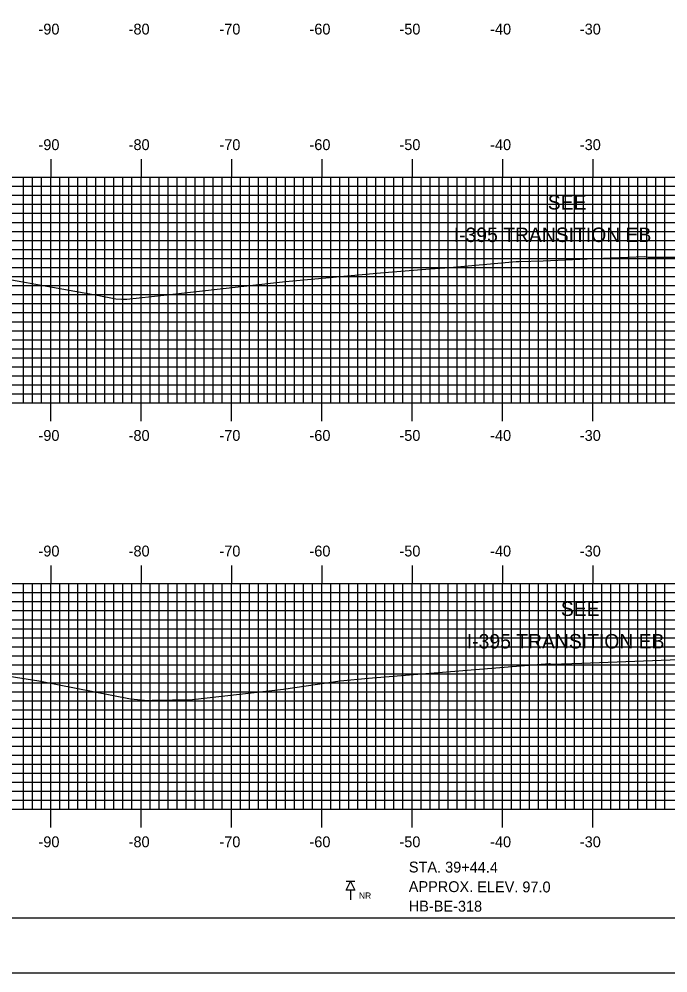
# Model space of a CAD drawing. Extents: x 844143 to 844486, y 363538 to 363758.
# Drawn here: x 844215 to 844286.8, y 363537.6 to 363643.2 of the extents above; entities that cross this region are included whole.
import ezdxf

# ---------------------------------------------------------------- set-up
doc = ezdxf.new("R2010")
doc.units = 0
for name, color, linetype in [('ANNOTATION', 7, 'Continuous'), ('BORDER', 7, 'Continuous'), ('BORING - NO REFUSAL', 7, 'Continuous'), ('H_V ANNOTATION', 7, 'Continuous'), ('M_Roadway_Centerline', 7, 'Continuous'), ('MAJOR', 7, 'Continuous'), ('MINOR', 7, 'Continuous'), ('PLOT BOUNDARY', 7, 'Continuous'), ('S_Roadway_Centerline', 7, 'Continuous')]:
    doc.layers.add(name, color=color, linetype=linetype)

msp = doc.modelspace()

# ---------------------------------------------------------------- linework, layer by layer
at = {"layer": 'BORDER'}
msp.add_lwpolyline([(844158.85, 363543.72), (844478.85, 363543.72), (844478.85, 363753.72), (844158.85, 363753.72)], close=True, dxfattribs=at)
at = {"layer": 'BORING - NO REFUSAL'}
for p, q in [((844252.13, 363547.72), (844251.17, 363547.72)), ((844251.65, 363546.76), (844251.65, 363545.7))]:
    msp.add_line(p, q, dxfattribs=at)
msp.add_lwpolyline([(844251.65, 363547.72), (844252.13, 363546.76), (844251.17, 363546.76)], close=True, dxfattribs=at)
at = {"layer": 'MAJOR'}
for p, q in [((844218.45, 363627.73), (844218.45, 363625.72)), ((844228.45, 363627.73), (844228.45, 363625.72)), ((844238.45, 363627.73), (844238.45, 363625.72)), ((844248.45, 363627.73), (844248.45, 363625.72)), ((844258.45, 363627.73), (844258.45, 363625.72)), ((844268.45, 363627.73), (844268.45, 363625.72)), ((844278.45, 363627.73), (844278.45, 363625.72)), ((844168.45, 363625.72), (844448.45, 363625.72)), ((844168.45, 363625.72), (844448.45, 363625.72)), ((844218.45, 363600.72), (844218.45, 363625.72)), ((844228.45, 363600.72), (844228.45, 363625.72)), ((844238.45, 363600.72), (844238.45, 363625.72)), ((844248.45, 363600.72), (844248.45, 363625.72)), ((844258.45, 363600.72), (844258.45, 363625.72)), ((844268.45, 363600.72), (844268.45, 363625.72)), ((844278.45, 363600.72), (844278.45, 363625.72)), ((844168.45, 363620.72), (844448.45, 363620.72)), ((844168.45, 363615.72), (844448.45, 363615.72)), ((844168.45, 363610.72), (844448.45, 363610.72)), ((844168.45, 363605.72), (844448.45, 363605.72)), ((844168.45, 363600.72), (844448.45, 363600.72)), ((844168.45, 363600.72), (844448.45, 363600.72)), ((844218.45, 363598.72), (844218.45, 363600.72)), ((844228.45, 363598.72), (844228.45, 363600.72)), ((844238.45, 363598.72), (844238.45, 363600.72)), ((844248.45, 363598.72), (844248.45, 363600.72)), ((844258.45, 363598.72), (844258.45, 363600.72)), ((844268.45, 363598.72), (844268.45, 363600.72)), ((844278.45, 363598.72), (844278.45, 363600.72)), ((844218.45, 363582.73), (844218.45, 363580.72)), ((844228.45, 363582.73), (844228.45, 363580.72)), ((844238.45, 363582.73), (844238.45, 363580.72)), ((844248.45, 363582.73), (844248.45, 363580.72)), ((844258.45, 363582.73), (844258.45, 363580.72)), ((844268.45, 363582.73), (844268.45, 363580.72)), ((844278.45, 363582.73), (844278.45, 363580.72)), ((844168.45, 363580.72), (844448.45, 363580.72)), ((844168.45, 363580.72), (844448.45, 363580.72)), ((844218.45, 363555.72), (844218.45, 363580.72)), ((844228.45, 363555.72), (844228.45, 363580.72)), ((844238.45, 363555.72), (844238.45, 363580.72)), ((844248.45, 363555.72), (844248.45, 363580.72)), ((844258.45, 363555.72), (844258.45, 363580.72)), ((844268.45, 363555.72), (844268.45, 363580.72)), ((844278.45, 363555.72), (844278.45, 363580.72)), ((844168.45, 363575.72), (844448.45, 363575.72)), ((844168.45, 363570.72), (844448.45, 363570.72)), ((844168.45, 363565.72), (844448.45, 363565.72)), ((844168.45, 363560.72), (844448.45, 363560.72)), ((844168.45, 363555.72), (844448.45, 363555.72)), ((844168.45, 363555.72), (844448.45, 363555.72)), ((844218.45, 363553.72), (844218.45, 363555.72)), ((844228.45, 363553.72), (844228.45, 363555.72)), ((844238.45, 363553.72), (844238.45, 363555.72)), ((844248.45, 363553.72), (844248.45, 363555.72)), ((844258.45, 363553.72), (844258.45, 363555.72)), ((844268.45, 363553.72), (844268.45, 363555.72)), ((844278.45, 363553.72), (844278.45, 363555.72))]:
    msp.add_line(p, q, dxfattribs=at)
at = {"layer": 'MINOR'}
for p, q in [((844215.45, 363600.72), (844215.45, 363625.72)), ((844216.45, 363600.72), (844216.45, 363625.72)), ((844217.45, 363600.72), (844217.45, 363625.72)), ((844219.45, 363600.72), (844219.45, 363625.72)), ((844220.45, 363600.72), (844220.45, 363625.72)), ((844221.45, 363600.72), (844221.45, 363625.72)), ((844222.45, 363600.72), (844222.45, 363625.72)), ((844223.45, 363600.72), (844223.45, 363625.72)), ((844224.45, 363600.72), (844224.45, 363625.72)), ((844225.45, 363600.72), (844225.45, 363625.72)), ((844226.45, 363600.72), (844226.45, 363625.72)), ((844227.45, 363600.72), (844227.45, 363625.72)), ((844229.45, 363600.72), (844229.45, 363625.72)), ((844230.45, 363600.72), (844230.45, 363625.72)), ((844231.45, 363600.72), (844231.45, 363625.72)), ((844232.45, 363600.72), (844232.45, 363625.72)), ((844233.45, 363600.72), (844233.45, 363625.72)), ((844234.45, 363600.72), (844234.45, 363625.72)), ((844235.45, 363600.72), (844235.45, 363625.72)), ((844236.45, 363600.72), (844236.45, 363625.72)), ((844237.45, 363600.72), (844237.45, 363625.72)), ((844239.45, 363600.72), (844239.45, 363625.72)), ((844240.45, 363600.72), (844240.45, 363625.72)), ((844241.45, 363600.72), (844241.45, 363625.72)), ((844242.45, 363600.72), (844242.45, 363625.72)), ((844243.45, 363600.72), (844243.45, 363625.72)), ((844244.45, 363600.72), (844244.45, 363625.72)), ((844245.45, 363600.72), (844245.45, 363625.72)), ((844246.45, 363600.72), (844246.45, 363625.72)), ((844247.45, 363600.72), (844247.45, 363625.72)), ((844249.45, 363600.72), (844249.45, 363625.72)), ((844250.45, 363600.72), (844250.45, 363625.72)), ((844251.45, 363600.72), (844251.45, 363625.72)), ((844252.45, 363600.72), (844252.45, 363625.72)), ((844253.45, 363600.72), (844253.45, 363625.72)), ((844254.45, 363600.72), (844254.45, 363625.72)), ((844255.45, 363600.72), (844255.45, 363625.72)), ((844256.45, 363600.72), (844256.45, 363625.72)), ((844257.45, 363600.72), (844257.45, 363625.72)), ((844259.45, 363600.72), (844259.45, 363625.72)), ((844260.45, 363600.72), (844260.45, 363625.72)), ((844261.45, 363600.72), (844261.45, 363625.72)), ((844262.45, 363600.72), (844262.45, 363625.72)), ((844263.45, 363600.72), (844263.45, 363625.72)), ((844264.45, 363600.72), (844264.45, 363625.72)), ((844265.45, 363600.72), (844265.45, 363625.72)), ((844266.45, 363600.72), (844266.45, 363625.72)), ((844267.45, 363600.72), (844267.45, 363625.72)), ((844269.45, 363600.72), (844269.45, 363625.72)), ((844270.45, 363600.72), (844270.45, 363625.72)), ((844271.45, 363600.72), (844271.45, 363625.72)), ((844272.45, 363600.72), (844272.45, 363625.72)), ((844273.45, 363600.72), (844273.45, 363625.72)), ((844274.45, 363600.72), (844274.45, 363625.72)), ((844275.45, 363600.72), (844275.45, 363625.72)), ((844276.45, 363600.72), (844276.45, 363625.72)), ((844277.45, 363600.72), (844277.45, 363625.72)), ((844279.45, 363600.72), (844279.45, 363625.72)), ((844280.45, 363600.72), (844280.45, 363625.72)), ((844281.45, 363600.72), (844281.45, 363625.72)), ((844282.45, 363600.72), (844282.45, 363625.72)), ((844283.45, 363600.72), (844283.45, 363625.72)), ((844284.45, 363600.72), (844284.45, 363625.72)), ((844285.45, 363600.72), (844285.45, 363625.72)), ((844286.45, 363600.72), (844286.45, 363625.72)), ((844168.45, 363624.72), (844448.45, 363624.72)), ((844168.45, 363623.72), (844448.45, 363623.72)), ((844168.45, 363622.72), (844448.45, 363622.72)), ((844168.45, 363621.72), (844448.45, 363621.72)), ((844168.45, 363619.72), (844448.45, 363619.72)), ((844168.45, 363618.72), (844448.45, 363618.72)), ((844168.45, 363617.72), (844448.45, 363617.72)), ((844168.45, 363616.72), (844448.45, 363616.72)), ((844168.45, 363614.72), (844448.45, 363614.72)), ((844168.45, 363613.72), (844448.45, 363613.72)), ((844168.45, 363612.72), (844448.45, 363612.72)), ((844168.45, 363611.72), (844448.45, 363611.72)), ((844168.45, 363609.72), (844448.45, 363609.72)), ((844168.45, 363608.72), (844448.45, 363608.72)), ((844168.45, 363607.72), (844448.45, 363607.72)), ((844168.45, 363606.72), (844448.45, 363606.72)), ((844168.45, 363604.72), (844448.45, 363604.72)), ((844168.45, 363603.72), (844448.45, 363603.72)), ((844168.45, 363602.72), (844448.45, 363602.72)), ((844168.45, 363601.72), (844448.45, 363601.72)), ((844215.45, 363555.72), (844215.45, 363580.72)), ((844216.45, 363555.72), (844216.45, 363580.72)), ((844217.45, 363555.72), (844217.45, 363580.72)), ((844219.45, 363555.72), (844219.45, 363580.72)), ((844220.45, 363555.72), (844220.45, 363580.72)), ((844221.45, 363555.72), (844221.45, 363580.72)), ((844222.45, 363555.72), (844222.45, 363580.72)), ((844223.45, 363555.72), (844223.45, 363580.72)), ((844224.45, 363555.72), (844224.45, 363580.72)), ((844225.45, 363555.72), (844225.45, 363580.72)), ((844226.45, 363555.72), (844226.45, 363580.72)), ((844227.45, 363555.72), (844227.45, 363580.72)), ((844229.45, 363555.72), (844229.45, 363580.72)), ((844230.45, 363555.72), (844230.45, 363580.72)), ((844231.45, 363555.72), (844231.45, 363580.72)), ((844232.45, 363555.72), (844232.45, 363580.72)), ((844233.45, 363555.72), (844233.45, 363580.72)), ((844234.45, 363555.72), (844234.45, 363580.72)), ((844235.45, 363555.72), (844235.45, 363580.72)), ((844236.45, 363555.72), (844236.45, 363580.72)), ((844237.45, 363555.72), (844237.45, 363580.72)), ((844239.45, 363555.72), (844239.45, 363580.72)), ((844240.45, 363555.72), (844240.45, 363580.72)), ((844241.45, 363555.72), (844241.45, 363580.72)), ((844242.45, 363555.72), (844242.45, 363580.72)), ((844243.45, 363555.72), (844243.45, 363580.72)), ((844244.45, 363555.72), (844244.45, 363580.72)), ((844245.45, 363555.72), (844245.45, 363580.72)), ((844246.45, 363555.72), (844246.45, 363580.72)), ((844247.45, 363555.72), (844247.45, 363580.72)), ((844249.45, 363555.72), (844249.45, 363580.72)), ((844250.45, 363555.72), (844250.45, 363580.72)), ((844251.45, 363555.72), (844251.45, 363580.72)), ((844252.45, 363555.72), (844252.45, 363580.72)), ((844253.45, 363555.72), (844253.45, 363580.72)), ((844254.45, 363555.72), (844254.45, 363580.72)), ((844255.45, 363555.72), (844255.45, 363580.72)), ((844256.45, 363555.72), (844256.45, 363580.72)), ((844257.45, 363555.72), (844257.45, 363580.72)), ((844259.45, 363555.72), (844259.45, 363580.72)), ((844260.45, 363555.72), (844260.45, 363580.72)), ((844261.45, 363555.72), (844261.45, 363580.72)), ((844262.45, 363555.72), (844262.45, 363580.72)), ((844263.45, 363555.72), (844263.45, 363580.72)), ((844264.45, 363555.72), (844264.45, 363580.72)), ((844265.45, 363555.72), (844265.45, 363580.72)), ((844266.45, 363555.72), (844266.45, 363580.72)), ((844267.45, 363555.72), (844267.45, 363580.72)), ((844269.45, 363555.72), (844269.45, 363580.72)), ((844270.45, 363555.72), (844270.45, 363580.72)), ((844271.45, 363555.72), (844271.45, 363580.72)), ((844272.45, 363555.72), (844272.45, 363580.72)), ((844273.45, 363555.72), (844273.45, 363580.72)), ((844274.45, 363555.72), (844274.45, 363580.72)), ((844275.45, 363555.72), (844275.45, 363580.72)), ((844276.45, 363555.72), (844276.45, 363580.72)), ((844277.45, 363555.72), (844277.45, 363580.72)), ((844279.45, 363555.72), (844279.45, 363580.72)), ((844280.45, 363555.72), (844280.45, 363580.72)), ((844281.45, 363555.72), (844281.45, 363580.72)), ((844282.45, 363555.72), (844282.45, 363580.72)), ((844283.45, 363555.72), (844283.45, 363580.72)), ((844284.45, 363555.72), (844284.45, 363580.72)), ((844285.45, 363555.72), (844285.45, 363580.72)), ((844286.45, 363555.72), (844286.45, 363580.72)), ((844168.45, 363579.72), (844448.45, 363579.72)), ((844168.45, 363578.72), (844448.45, 363578.72)), ((844168.45, 363577.72), (844448.45, 363577.72)), ((844168.45, 363576.72), (844448.45, 363576.72)), ((844168.45, 363574.72), (844448.45, 363574.72)), ((844168.45, 363573.72), (844448.45, 363573.72)), ((844168.45, 363572.72), (844448.45, 363572.72)), ((844168.45, 363571.72), (844448.45, 363571.72)), ((844168.45, 363569.72), (844448.45, 363569.72)), ((844168.45, 363568.72), (844448.45, 363568.72)), ((844168.45, 363567.72), (844448.45, 363567.72)), ((844168.45, 363566.72), (844448.45, 363566.72)), ((844168.45, 363564.72), (844448.45, 363564.72)), ((844168.45, 363563.72), (844448.45, 363563.72)), ((844168.45, 363562.72), (844448.45, 363562.72)), ((844168.45, 363561.72), (844448.45, 363561.72)), ((844168.45, 363559.72), (844448.45, 363559.72)), ((844168.45, 363558.72), (844448.45, 363558.72)), ((844168.45, 363557.72), (844448.45, 363557.72)), ((844168.45, 363556.72), (844448.45, 363556.72))]:
    msp.add_line(p, q, dxfattribs=at)
at = {"layer": 'PLOT BOUNDARY'}
msp.add_lwpolyline([(844142.66, 363537.6), (844482.66, 363537.6), (844482.66, 363757.6), (844142.66, 363757.6)], close=True, dxfattribs=at)
at = {"layer": 'S_Roadway_Centerline'}
for points in [[(844208.3, 363615.37), (844223.61, 363612.64), (844225.67, 363612.24), (844226.33, 363612.2), (844226.89, 363612.22), (844230.97, 363612.64), (844244.44, 363614.16), (844255.38, 363615.15), (844260.47, 363615.56), (844262.64, 363615.71), (844269.98, 363616.38), (844270.29, 363616.38), (844272.98, 363616.46), (844277.84, 363616.67), (844284.16, 363616.92), (844284.6, 363616.85), (844285.11, 363616.86), (844289.28, 363616.87)], [(844213.14, 363570.56), (844217.13, 363569.96), (844227.3, 363567.96), (844229.25, 363567.77), (844229.68, 363567.81), (844234.14, 363567.89), (844244.24, 363569.04), (844250.49, 363569.94), (844253.63, 363570.24), (844263.64, 363571.06), (844271.81, 363571.72), (844273.66, 363571.88), (844273.88, 363571.79), (844277.25, 363571.91), (844287.98, 363572.31)]]:
    msp.add_lwpolyline(points, dxfattribs=at)

# ---------------------------------------------------------------- texts
at = {"layer": 'ANNOTATION'}
for s, p in [('SEE', (844273.48, 363622.14)), ('I-395 TRANSITION EB', (844263.07, 363618.54)), ('SEE', (844274.93, 363577.13)), ('I-395 TRANSITION EB', (844264.52, 363573.53))]:
    msp.add_text(s, height=1.6, dxfattribs=at).set_placement(p)
at = {"layer": 'BORING - NO REFUSAL'}
for s, p in [('STA. 39+44.4', (844258.1, 363548.73)), ('APPROX. ELEV. 97.0', (844258.09, 363546.57)), ('HB-BE-318', (844258.09, 363544.41))]:
    msp.add_text(s, height=1.2, rotation=359.8142, dxfattribs=at).set_placement(p)
msp.add_text('NR', height=0.7, dxfattribs=at).set_placement((844252.58, 363545.81))
at = {"layer": 'H_V ANNOTATION'}
for s, p in [('-90', (844217.1, 363641.52)), ('-80', (844227.08, 363641.52)), ('-70', (844237.13, 363641.52)), ('-60', (844247.1, 363641.52)), ('-50', (844257.06, 363641.52)), ('-40', (844267.1, 363641.52)), ('-30', (844277.03, 363641.52)), ('-90', (844217.1, 363628.72)), ('-80', (844227.08, 363628.72)), ('-70', (844237.13, 363628.72)), ('-60', (844247.1, 363628.72)), ('-50', (844257.06, 363628.72)), ('-40', (844267.1, 363628.72)), ('-30', (844277.03, 363628.72)), ('-90', (844217.1, 363596.52)), ('-80', (844227.08, 363596.52)), ('-70', (844237.13, 363596.52)), ('-60', (844247.1, 363596.52)), ('-50', (844257.06, 363596.52)), ('-40', (844267.1, 363596.52)), ('-30', (844277.03, 363596.52)), ('-90', (844217.1, 363583.72)), ('-80', (844227.08, 363583.72)), ('-70', (844237.13, 363583.72)), ('-60', (844247.1, 363583.72)), ('-50', (844257.06, 363583.72)), ('-40', (844267.1, 363583.72)), ('-30', (844277.03, 363583.72)), ('-90', (844217.1, 363551.52)), ('-80', (844227.08, 363551.52)), ('-70', (844237.13, 363551.52)), ('-60', (844247.1, 363551.52)), ('-50', (844257.06, 363551.52)), ('-40', (844267.1, 363551.52)), ('-30', (844277.03, 363551.52))]:
    msp.add_text(s, height=1.2, dxfattribs=at).set_placement(p)
at = {"layer": 'M_Roadway_Centerline'}
for s, p in [('C', (844284.16, 363616.92)), ('L', (844284.16, 363616.91))]:
    msp.add_text(s, height=0.0146, dxfattribs=at).set_placement(p)

doc.saveas('drawing.dxf')
